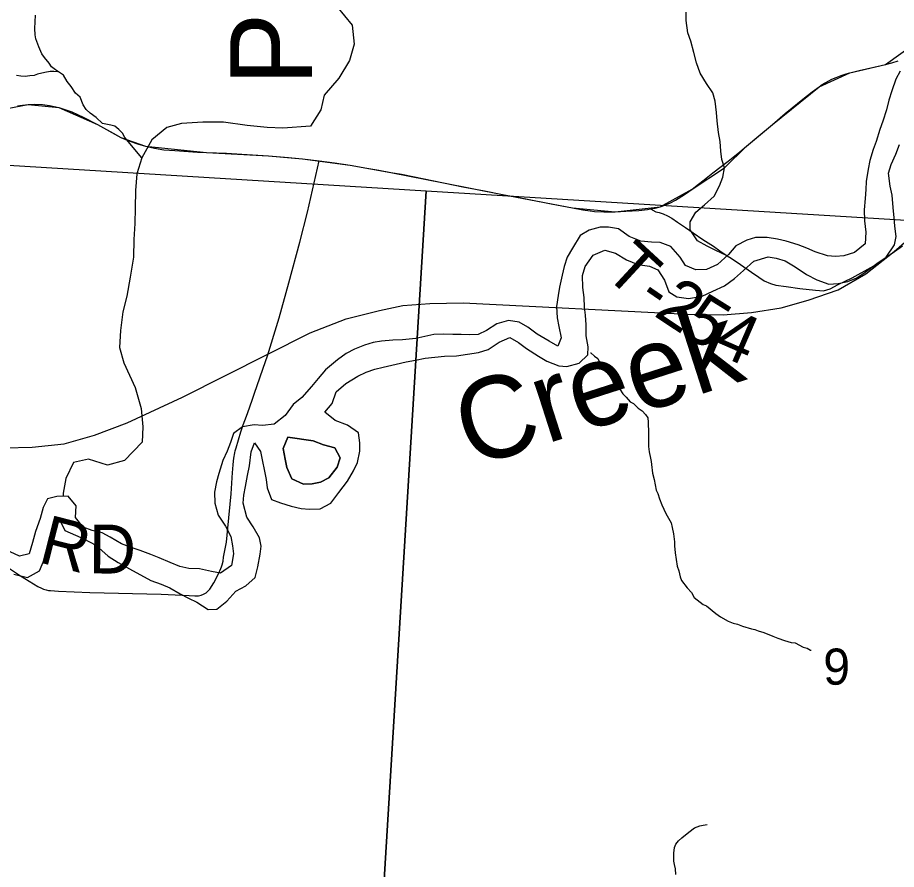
# Model space of a CAD drawing. Extents: x 0 to 82.7, y -0.2 to 22.
# Drawn here: x 4.353 to 5.374, y 18.621 to 19.61 of the extents above; entities that cross this region are included whole.
import ezdxf

# ---------------------------------------------------------------- set-up
doc = ezdxf.new("R2010")
doc.units = 0
for name, color, linetype in [('GM_X_County_Road', 7, 'Continuous'), ('GM_X_County_Road_Text', 7, 'Continuous'), ('GM_X_Minor_River', 7, 'Continuous'), ('GM_X_Minor_River_Text', 7, 'Continuous'), ('GM_X_Rail_Line', 7, 'Continuous'), ('GM_X_Section', 7, 'Continuous'), ('GM_X_Section_Text', 7, 'Continuous'), ('GM_X_State_Route', 7, 'Continuous'), ('GM_X_Township_Road', 7, 'Continuous'), ('GM_X_Township_Road_Text', 7, 'Continuous'), ('SH_Text', 7, 'Continuous')]:
    doc.layers.add(name, color=color, linetype=linetype)

msp = doc.modelspace()

# ---------------------------------------------------------------- linework, layer by layer
at = {"layer": 'GM_X_County_Road'}
for points in [[(5.0884, 19.388), (5.0937, 19.3891), (5.0996, 19.3906), (5.105, 19.3924), (5.1116, 19.3953), (5.1174, 19.3984), (5.1204, 19.4002), (5.1288, 19.4056), (5.1366, 19.4112), (5.1441, 19.4168), (5.1492, 19.4207), (5.1606, 19.4298), (5.1783, 19.4435), (5.192, 19.4545), (5.1997, 19.4609), (5.214, 19.473), (5.2299, 19.4862), (5.2448, 19.4989), (5.267, 19.5172), (5.2758, 19.5239), (5.284, 19.5297), (5.2877, 19.5324), (5.291, 19.5344), (5.2917, 19.5347), (5.2986, 19.5385), (5.3037, 19.5408), (5.3097, 19.543), (5.3156, 19.5449), (5.3195, 19.546), (5.3306, 19.5488), (5.3475, 19.5528), (5.3611, 19.5557), (5.3683, 19.5576), (5.3758, 19.56)], [(4.3429, 18.9715), (4.3567, 18.9622), (4.3769, 18.9498), (4.3811, 18.9478), (4.3836, 18.9468), (4.3865, 18.946), (4.3895, 18.9453), (4.3916, 18.945), (4.4009, 18.9443), (4.4373, 18.943), (4.5201, 18.9409), (4.5525, 18.9392), (4.5593, 18.939), (4.5636, 18.9391), (4.5666, 18.9396), (4.5692, 18.9408), (4.5725, 18.9426), (4.5751, 18.945), (4.5767, 18.9468), (4.5812, 18.954), (4.5868, 18.9647), (4.5896, 18.9706), (4.5904, 18.9728), (4.5911, 18.975), (4.5923, 18.9794), (4.5927, 18.984), (4.5959, 19.0011), (4.5974, 19.0174), (4.6014, 19.0572), (4.6031, 19.0822), (4.6035, 19.0859), (4.6039, 19.0916), (4.6047, 19.0989), (4.6057, 19.1048), (4.6062, 19.1072), (4.6072, 19.1109), (4.6127, 19.1293), (4.6155, 19.1375), (4.6191, 19.1476), (4.6226, 19.1572), (4.6267, 19.1685), (4.6287, 19.1741), (4.6414, 19.2108), (4.6438, 19.2177), (4.6557, 19.2566), (4.6571, 19.2617), (4.6683, 19.3022), (4.681, 19.3495), (4.69, 19.3845), (4.7038, 19.444)], [(4.7038, 19.444), (4.7216, 19.4414), (4.7396, 19.4387), (4.7568, 19.4359), (4.773, 19.4331), (4.7869, 19.4304), (4.7991, 19.4283), (4.8257, 19.4229), (4.848, 19.4183)], [(4.848, 19.4183), (4.8704, 19.4136), (4.8954, 19.4089), (4.9166, 19.4047), (4.9435, 19.3996), (4.9728, 19.3938), (4.9978, 19.3892), (5.0099, 19.3869), (5.0184, 19.3857), (5.0233, 19.3851), (5.0342, 19.3846), (5.0474, 19.3848), (5.0597, 19.3855), (5.0746, 19.3864), (5.0846, 19.3874), (5.0884, 19.388)]]:
    msp.add_lwpolyline(points, dxfattribs=at)
at = {"layer": 'GM_X_Minor_River'}
for points in [[(4.724, 19.623), (4.742, 19.6013), (4.7442, 19.5792), (4.7387, 19.5603), (4.7265, 19.5398), (4.7093, 19.5202), (4.7057, 19.5031), (4.6935, 19.4842), (4.6616, 19.4817), (4.6434, 19.4826), (4.6199, 19.485), (4.5926, 19.4889), (4.5687, 19.4886), (4.5437, 19.4873), (4.5266, 19.4824), (4.5094, 19.4681), (4.4979, 19.4473), (4.4921, 19.4287), (4.4905, 19.4093), (4.4899, 19.3888), (4.4898, 19.371), (4.4886, 19.3527), (4.4881, 19.3322), (4.4841, 19.3087), (4.4802, 19.2867), (4.4755, 19.2685), (4.4731, 19.2469), (4.4718, 19.2271), (4.477, 19.2093), (4.4901, 19.1807), (4.4971, 19.1564), (4.4989, 19.1351), (4.498, 19.1173), (4.4778, 19.0961), (4.458, 19.0905), (4.436, 19.0975), (4.4186, 19.0938), (4.4094, 19.0752), (4.4066, 19.0581), (4.4066, 19.0546)], [(4.4979, 19.4473), (4.478, 19.471), (4.4754, 19.476), (4.4712, 19.4802), (4.4664, 19.4841), (4.4618, 19.4853), (4.4577, 19.4861), (4.452, 19.4873), (4.4448, 19.4943), (4.4377, 19.4993), (4.4332, 19.5035), (4.4295, 19.5089), (4.4261, 19.5177), (4.4209, 19.5223), (4.4157, 19.53), (4.4112, 19.5361), (4.4067, 19.5434), (4.3977, 19.5496), (4.3928, 19.5531), (4.3902, 19.5573), (4.3846, 19.5638), (4.3816, 19.568), (4.3783, 19.5764), (4.3746, 19.5856), (4.3739, 19.5902), (4.3736, 19.5974), (4.3741, 19.613)], [(5.1771, 19.3335), (5.1641, 19.34), (5.1542, 19.345), (5.1429, 19.3511), (5.1343, 19.3637), (5.1344, 19.3732), (5.1409, 19.3842), (5.1508, 19.3928), (5.1622, 19.403), (5.1684, 19.4147), (5.1722, 19.4249), (5.1742, 19.4359), (5.1712, 19.4454), (5.1698, 19.4553), (5.1691, 19.4663), (5.1673, 19.4766), (5.1658, 19.4902), (5.1648, 19.5001), (5.1633, 19.513), (5.1608, 19.5229), (5.1533, 19.5336), (5.1458, 19.5458), (5.1417, 19.5576), (5.1387, 19.5697), (5.135, 19.5826), (5.1317, 19.5925), (5.1295, 19.6066), (5.1296, 19.6164)], [(4.4003, 19.5473), (4.3954, 19.5477), (4.3912, 19.5474), (4.3851, 19.5463), (4.3768, 19.5445), (4.3726, 19.5431), (4.3676, 19.5424), (4.3623, 19.5417), (4.3574, 19.5421), (4.3521, 19.5429)], [(5.3781, 19.5481), (5.3731, 19.5386), (5.3686, 19.5253), (5.3651, 19.5143), (5.3621, 19.5029), (5.3579, 19.49), (5.3545, 19.4801)], [(5.3545, 19.4801), (5.3503, 19.4664), (5.3469, 19.4569), (5.343, 19.4444), (5.3408, 19.4341), (5.3388, 19.4201), (5.3381, 19.4106), (5.3373, 19.4003), (5.3362, 19.387), (5.3369, 19.3741), (5.3384, 19.3611), (5.3373, 19.3474), (5.3251, 19.3376), (5.3129, 19.3338), (5.3031, 19.333), (5.2936, 19.3338), (5.2795, 19.3384), (5.2696, 19.3426), (5.2597, 19.3464), (5.2457, 19.3506), (5.2358, 19.3529), (5.2236, 19.3551), (5.21, 19.3548), (5.2001, 19.3517), (5.1875, 19.3453), (5.1788, 19.335), (5.1662, 19.3236), (5.1533, 19.3179), (5.1408, 19.3172), (5.129, 19.3225), (5.1229, 19.332), (5.1119, 19.3446), (5.0993, 19.3492), (5.0895, 19.3496), (5.0769, 19.3507), (5.0636, 19.356), (5.0511, 19.3648), (5.0397, 19.3671), (5.0298, 19.3671), (5.0169, 19.3633), (5.0066, 19.3572), (4.9979, 19.3424), (4.9914, 19.3321), (4.988, 19.3211), (4.9857, 19.3112), (4.9826, 19.2972), (4.9811, 19.2877), (4.9792, 19.2748), (4.9799, 19.2618), (4.9818, 19.2516), (4.9845, 19.2386), (4.9807, 19.2288), (4.9708, 19.2345), (4.9567, 19.2428), (4.9457, 19.2508), (4.9359, 19.2565), (4.9233, 19.2585), (4.91, 19.2547), (4.8978, 19.2471), (4.8883, 19.2425), (4.8781, 19.2421), (4.8686, 19.2425), (4.8587, 19.2425), (4.8484, 19.2429), (4.8366, 19.2422), (4.8264, 19.2399), (4.8157, 19.2376), (4.8005, 19.2361), (4.7891, 19.2358), (4.7758, 19.2346), (4.7663, 19.2331), (4.7561, 19.2301), (4.7447, 19.2252), (4.7348, 19.2202), (4.7249, 19.213), (4.7108, 19.2012), (4.7024, 19.1914), (4.6948, 19.1819), (4.6834, 19.1693), (4.6735, 19.161), (4.664, 19.1484), (4.6515, 19.1382), (4.6378, 19.1367), (4.6283, 19.1374), (4.6146, 19.1352), (4.604, 19.1276), (4.6005, 19.1169), (4.5967, 19.1071), (4.5918, 19.096), (4.5872, 19.0808), (4.5845, 19.0713), (4.5822, 19.0592), (4.5826, 19.0466), (4.5864, 19.0326), (4.5948, 19.02), (4.6012, 19.0078), (4.6031, 18.9972), (4.6042, 18.9877), (4.602, 18.9744), (4.589, 18.9653), (4.5788, 18.9672)], [(4.6711, 19.043), (4.6829, 19.0403), (4.6924, 19.0396), (4.7049, 19.04), (4.7171, 19.0464), (4.7266, 19.0589), (4.7365, 19.0722), (4.7434, 19.084), (4.7483, 19.0939), (4.751, 19.1068), (4.751, 19.1167), (4.7491, 19.1281), (4.7366, 19.1369), (4.7221, 19.1426), (4.7103, 19.1521), (4.7187, 19.1623), (4.7233, 19.1756), (4.7347, 19.1855), (4.7484, 19.1939), (4.7583, 19.1988), (4.7682, 19.2022), (4.778, 19.2045), (4.7929, 19.2079), (4.8046, 19.2105), (4.8153, 19.2124), (4.8267, 19.2147), (4.8377, 19.2162), (4.8491, 19.217), (4.8632, 19.2177), (4.8757, 19.2196), (4.8886, 19.2215), (4.8997, 19.2249), (4.9126, 19.2333), (4.9251, 19.239), (4.935, 19.2329), (4.9445, 19.226), (4.9582, 19.2173), (4.9681, 19.2112), (4.9818, 19.2058), (4.9913, 19.2051), (5.0053, 19.2092), (5.0156, 19.2187), (5.016, 19.2282), (5.0137, 19.2408), (5.0137, 19.2537), (5.013, 19.2647), (5.0118, 19.2742), (5.0111, 19.2853), (5.0099, 19.297), (5.0092, 19.3107), (5.0126, 19.3214), (5.0218, 19.3343), (5.0351, 19.3404), (5.0476, 19.3369), (5.0605, 19.3289), (5.0734, 19.3236), (5.0871, 19.3217), (5.0966, 19.3175), (5.1046, 19.3053), (5.1095, 19.292), (5.119, 19.2859), (5.1323, 19.284), (5.1483, 19.2867), (5.1608, 19.2927), (5.1741, 19.2988), (5.1859, 19.3075), (5.1962, 19.3167), (5.2084, 19.3273), (5.2247, 19.3326), (5.2342, 19.3311), (5.2445, 19.328), (5.2563, 19.3208), (5.2695, 19.312), (5.2813, 19.3059), (5.2954, 19.3006), (5.306, 19.3014), (5.3174, 19.304), (5.3277, 19.3082), (5.3376, 19.3146), (5.3509, 19.3249), (5.3619, 19.3321), (5.3714, 19.3465), (5.3733, 19.356), (5.3718, 19.3682), (5.3711, 19.3777), (5.3699, 19.3899), (5.3688, 19.4039), (5.3665, 19.4146), (5.3646, 19.4294), (5.3677, 19.4397), (5.373, 19.4518), (5.3772, 19.4629)], [(5.0186, 19.2212), (5.0191, 19.221), (5.0232, 19.2171), (5.027, 19.2144), (5.0292, 19.2102), (5.0337, 19.2064), (5.0378, 19.2006), (5.0419, 19.1945), (5.0457, 19.1891), (5.0501, 19.1826), (5.0528, 19.1788), (5.0561, 19.1734), (5.0599, 19.1695), (5.0647, 19.1642), (5.0685, 19.1622), (5.0741, 19.1568), (5.0787, 19.1537), (5.0824, 19.1495), (5.085, 19.1457), (5.0857, 19.1407), (5.0859, 19.1278), (5.0858, 19.1122), (5.0868, 19.1061), (5.0883, 19.0989), (5.089, 19.0951), (5.0893, 19.0913), (5.0907, 19.0814), (5.0925, 19.0741), (5.095, 19.0616), (5.0969, 19.0577), (5.0987, 19.0516), (5.1013, 19.0448), (5.1061, 19.0345), (5.1124, 19.0237), (5.1135, 19.0184), (5.1149, 19.0108), (5.116, 19.0016), (5.1163, 18.9971), (5.117, 18.9891), (5.1191, 18.9735), (5.1213, 18.9681), (5.1227, 18.9609), (5.1242, 18.9567), (5.1309, 18.9483), (5.1358, 18.9429), (5.1391, 18.9371), (5.1493, 18.929), (5.1531, 18.9275), (5.164, 18.9186), (5.1696, 18.9147), (5.1786, 18.9097), (5.1843, 18.9073), (5.1892, 18.9061), (5.1949, 18.9038), (5.2055, 18.9006), (5.2093, 18.8998), (5.2134, 18.8982), (5.2198, 18.8966), (5.2304, 18.8923), (5.2361, 18.8899), (5.244, 18.8872), (5.2516, 18.8848), (5.2561, 18.8844), (5.2656, 18.8793), (5.2701, 18.8781), (5.2742, 18.8761), (5.2749, 18.8759)], [(4.6674, 19.1233), (4.6617, 19.11), (4.664, 19.0975), (4.6659, 19.088), (4.672, 19.0747), (4.6856, 19.0686), (4.6955, 19.069), (4.705, 19.0709)], [(4.6674, 19.1233), (4.6967, 19.1188), (4.7088, 19.1142), (4.7218, 19.1108), (4.7278, 19.0993), (4.7244, 19.0883), (4.7149, 19.0758), (4.705, 19.0709), (4.6955, 19.069), (4.6856, 19.0686), (4.672, 19.0747), (4.6659, 19.088), (4.664, 19.0975), (4.6617, 19.11), (4.6674, 19.1233)], [(4.705, 19.0709), (4.7149, 19.0758), (4.7244, 19.0883), (4.7278, 19.0993), (4.7218, 19.1108), (4.7088, 19.1142), (4.6967, 19.1188), (4.6674, 19.1233)], [(4.3491, 18.9642), (4.3651, 18.9604), (4.3788, 18.968), (4.3853, 18.9828), (4.3895, 18.9931), (4.3921, 19.0033), (4.3959, 19.0159), (4.402, 19.0277), (4.4085, 19.0147), (4.4206, 19.0094), (4.4305, 19.0052), (4.4442, 18.998), (4.4586, 18.985), (4.4704, 18.9778), (4.4833, 18.9702), (4.508, 18.9569), (4.5202, 18.9527), (4.5304, 18.9481), (4.5422, 18.9413), (4.5521, 18.9363), (4.5616, 18.9317), (4.5749, 18.923), (4.5848, 18.9234), (4.5966, 18.9328), (4.6068, 18.9446), (4.6186, 18.9507), (4.6293, 18.9602), (4.6323, 18.9727), (4.635, 18.9872), (4.6361, 18.9967), (4.6342, 19.0062), (4.627, 19.0191), (4.6198, 19.0305), (4.6153, 19.0465), (4.616, 19.056), (4.6179, 19.0659), (4.6206, 19.0788), (4.6229, 19.0898), (4.6248, 19.1062), (4.6286, 19.1164), (4.6354, 19.1065), (4.6419, 19.0742), (4.6434, 19.0643), (4.6483, 19.051), (4.6586, 19.0468), (4.6711, 19.043)], [(4.5788, 18.9672), (4.5647, 18.9702), (4.5522, 18.9706), (4.5419, 18.9729), (4.5305, 18.9775), (4.518, 18.9832), (4.5081, 18.987), (4.4959, 18.9916), (4.4864, 18.9946), (4.4743, 18.9992), (4.461, 19.0072), (4.4515, 19.0122), (4.4401, 19.0148), (4.4298, 19.0186), (4.4207, 19.03), (4.4215, 19.0433), (4.4124, 19.0548), (4.399, 19.0544), (4.3884, 19.0514), (4.3831, 19.0415), (4.3796, 19.0289), (4.3743, 19.0137), (4.3709, 19.0008), (4.3671, 18.9879), (4.3557, 18.9849), (4.3447, 18.9902)], [(5.1176, 18.6156), (5.1173, 18.6221), (5.1162, 18.627), (5.1155, 18.6312), (5.1152, 18.6361), (5.1152, 18.6403), (5.116, 18.6468), (5.1176, 18.6509), (5.1207, 18.6547), (5.1245, 18.6581), (5.1329, 18.6648), (5.1395, 18.6696), (5.1456, 18.6722), (5.1494, 18.6729), (5.1539, 18.6736)]]:
    msp.add_lwpolyline(points, dxfattribs=at)
at = {"layer": 'GM_X_Rail_Line'}
msp.add_lwpolyline([(4.3384, 19.1108), (4.3706, 19.1116), (4.4075, 19.1156), (4.4429, 19.1253), (4.4807, 19.1398), (4.5451, 19.1695), (4.6931, 19.2444), (4.7349, 19.2605), (4.7735, 19.2701), (4.8009, 19.2758), (4.8322, 19.2782), (4.8708, 19.279), (5.1314, 19.2661), (5.1725, 19.2653), (5.2054, 19.2677), (5.24, 19.2733), (5.2714, 19.2822), (5.306, 19.2943), (5.3382, 19.3128), (5.3711, 19.3385), (5.4065, 19.3691)], dxfattribs=at)
at = {"layer": 'GM_X_Section'}
for points in [[(3.8012, 19.4723), (4.8277, 19.4092), (4.7658, 18.3936), (3.7502, 18.459)], [(4.8277, 19.4092), (5.8471, 19.3468), (5.7783, 18.3279), (4.7658, 18.3936)]]:
    msp.add_lwpolyline(points, close=True, dxfattribs=at)
at = {"layer": 'GM_X_State_Route'}
for points in [[(5.0884, 19.388), (5.0937, 19.3891), (5.0996, 19.3906), (5.105, 19.3924), (5.1116, 19.3953), (5.1174, 19.3984), (5.1204, 19.4002), (5.1288, 19.4056), (5.1366, 19.4112), (5.1441, 19.4168), (5.1492, 19.4207), (5.1606, 19.4298), (5.1783, 19.4435), (5.192, 19.4545), (5.1997, 19.4609), (5.214, 19.473), (5.2299, 19.4862), (5.2448, 19.4989), (5.267, 19.5172), (5.2758, 19.5239), (5.284, 19.5297), (5.2877, 19.5324), (5.291, 19.5344), (5.2917, 19.5347), (5.2986, 19.5385), (5.3037, 19.5408), (5.3097, 19.543), (5.3156, 19.5449), (5.3195, 19.546), (5.3306, 19.5488), (5.3475, 19.5528), (5.3611, 19.5557), (5.3683, 19.5576), (5.3758, 19.56)], [(4.3534, 19.5076), (4.3538, 19.5076), (4.356, 19.5081), (4.3656, 19.5093), (4.3733, 19.5097), (4.3825, 19.5091), (4.3904, 19.5082), (4.4012, 19.5057), (4.4165, 19.5008), (4.4296, 19.4947), (4.4463, 19.4859), (4.4643, 19.4762), (4.4735, 19.4711), (4.4827, 19.4671), (4.4937, 19.4633), (4.5021, 19.461), (4.5125, 19.4586), (4.5233, 19.4568), (4.5362, 19.4559), (4.5625, 19.4541), (4.5727, 19.4536), (4.5961, 19.4527), (4.62, 19.4514), (4.6446, 19.4497), (4.6679, 19.4477), (4.6843, 19.4461), (4.7038, 19.444)], [(4.7038, 19.444), (4.7216, 19.4414), (4.7396, 19.4387), (4.7568, 19.4359), (4.773, 19.4331), (4.7869, 19.4304), (4.7991, 19.4283), (4.8257, 19.4229), (4.848, 19.4183)], [(4.848, 19.4183), (4.8704, 19.4136), (4.8954, 19.4089), (4.9166, 19.4047), (4.9435, 19.3996), (4.9728, 19.3938), (4.9978, 19.3892), (5.0099, 19.3869), (5.0184, 19.3857), (5.0233, 19.3851), (5.0342, 19.3846), (5.0474, 19.3848), (5.0597, 19.3855), (5.0746, 19.3864), (5.0846, 19.3874), (5.0884, 19.388)]]:
    msp.add_lwpolyline(points, dxfattribs=at)
at = {"layer": 'GM_X_Township_Road'}
for points in [[(4.3534, 19.5076), (4.3538, 19.5076), (4.356, 19.5081), (4.3656, 19.5093), (4.3733, 19.5097), (4.3825, 19.5091), (4.3904, 19.5082), (4.4012, 19.5057), (4.4165, 19.5008), (4.4296, 19.4947), (4.4463, 19.4859), (4.4643, 19.4762), (4.4735, 19.4711), (4.4827, 19.4671), (4.4937, 19.4633), (4.5021, 19.461), (4.5125, 19.4586), (4.5233, 19.4568), (4.5362, 19.4559), (4.5625, 19.4541), (4.5727, 19.4536), (4.5961, 19.4527), (4.62, 19.4514), (4.6446, 19.4497), (4.6679, 19.4477), (4.6843, 19.4461), (4.7038, 19.444)], [(4.7038, 19.444), (4.7216, 19.4414), (4.7396, 19.4387), (4.7568, 19.4359), (4.773, 19.4331), (4.7869, 19.4304), (4.7991, 19.4283), (4.8257, 19.4229), (4.848, 19.4183)], [(4.848, 19.4183), (4.8704, 19.4136), (4.8954, 19.4089), (4.9166, 19.4047), (4.9435, 19.3996), (4.9728, 19.3938), (4.9978, 19.3892), (5.0099, 19.3869), (5.0184, 19.3857), (5.0233, 19.3851), (5.0342, 19.3846), (5.0474, 19.3848), (5.0597, 19.3855), (5.0746, 19.3864), (5.0846, 19.3874), (5.0884, 19.388)], [(5.0884, 19.388), (5.0943, 19.3846), (5.0984, 19.3839), (5.1031, 19.3824), (5.1081, 19.3802), (5.1131, 19.3772), (5.1197, 19.3728), (5.129, 19.3664), (5.1378, 19.3602), (5.1491, 19.3524), (5.1613, 19.3447), (5.1689, 19.3393), (5.1774, 19.3336), (5.182, 19.3311), (5.1927, 19.3234), (5.2054, 19.3146), (5.214, 19.3087), (5.2204, 19.3047), (5.2276, 19.3017), (5.2338, 19.2997), (5.2458, 19.2982), (5.2618, 19.2959), (5.28, 19.2937), (5.2891, 19.2932), (5.2968, 19.2955), (5.306, 19.3005), (5.3224, 19.308), (5.3475, 19.322), (5.3714, 19.3385), (5.3809, 19.3452)]]:
    msp.add_lwpolyline(points, dxfattribs=at)
at = {"layer": 'SH_Text'}
for p, q in [((5.3611, 19.5557), (5.3966, 19.5811)), ((5.3195, 19.546), (5.3611, 19.5557)), ((5.284, 19.5297), (5.3195, 19.546)), ((5.2299, 19.4862), (5.284, 19.5297)), ((4.3414, 19.5047), (4.3656, 19.5093)), ((4.3656, 19.5093), (4.4012, 19.5057)), ((4.4012, 19.5057), (4.4463, 19.4859)), ((4.4463, 19.4859), (4.4735, 19.4711)), ((5.1997, 19.4609), (5.2299, 19.4862)), ((4.4735, 19.4711), (4.5021, 19.461)), ((4.5021, 19.461), (4.5727, 19.4536)), ((5.1742, 19.4359), (5.1997, 19.4609)), ((4.5727, 19.4536), (4.6446, 19.4497)), ((4.6446, 19.4497), (4.6843, 19.4461)), ((4.6843, 19.4461), (4.7396, 19.4387)), ((4.7396, 19.4387), (4.7869, 19.4304)), ((4.7869, 19.4304), (4.848, 19.4183)), ((5.1366, 19.4112), (5.1742, 19.4359)), ((4.848, 19.4183), (4.9166, 19.4047)), ((5.0996, 19.3906), (5.1366, 19.4112)), ((4.9166, 19.4047), (4.9978, 19.3892)), ((4.9978, 19.3892), (5.0474, 19.3848)), ((5.0474, 19.3848), (5.0996, 19.3906))]:
    msp.add_line(p, q, dxfattribs=at)

# ---------------------------------------------------------------- texts
at = {"layer": 'GM_X_County_Road_Text'}
for s, rotation, p in [('R', 345.6618, (4.376, 18.9784)), ('D', 359.7169, (4.436, 18.965))]:
    msp.add_text(s, height=0.0568, rotation=rotation, dxfattribs=at).set_placement(p)
at = {"layer": 'GM_X_Minor_River_Text'}
for s, height, rotation, p in [('Poplar', 0.0947, 89.9998, (4.6951, 19.5312)), ('Creek', 0.09469, 17.799, (4.8799, 19.0872))]:
    msp.add_text(s, height=height, rotation=rotation, dxfattribs=at).set_placement(p)
at = {"layer": 'GM_X_Section_Text'}
msp.add_text('9', height=0.0419, rotation=0, dxfattribs=at).set_placement((5.2888, 18.8359))
at = {"layer": 'GM_X_Township_Road_Text'}
for s, rotation, p in [('T', 317.2658, (5.0324, 19.3132)), ('2', 326.4468, (5.0907, 19.265)), ('-', 325.3825, (5.0705, 19.2789)), ('5', 328.0685, (5.1213, 19.2447)), ('4', 336.5055, (5.1591, 19.222))]:
    msp.add_text(s, height=0.0568, rotation=rotation, dxfattribs=at).set_placement(p)

doc.saveas('drawing.dxf')
